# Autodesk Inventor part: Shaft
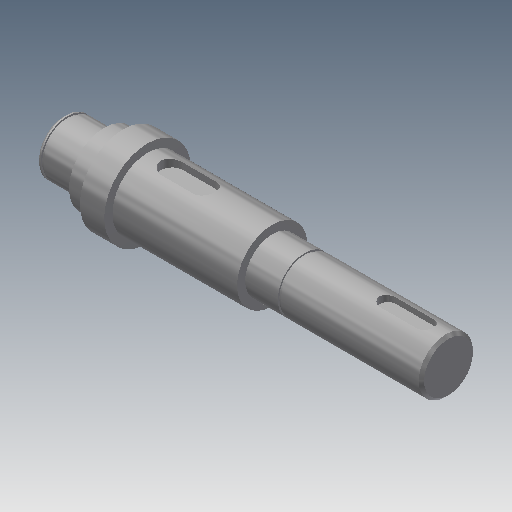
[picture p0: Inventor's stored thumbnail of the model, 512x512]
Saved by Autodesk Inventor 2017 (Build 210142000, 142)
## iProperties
Created: 2019-02
Part Number: Shaft
Material: Steel
Document SubType Name: Modeling
Designer: user
Density: 7.85 g/cm^3
Appearance: Steel
Mass: 468.646 g
Surface Area: 121.458 cm^2
Volume: 59.7002 cm^3
CustomPartVersion: 1
Author: user
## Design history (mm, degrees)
sketch "Main Sketch"
  geometry: L1 (0, 0)-(142, 0) reference; L2 (0, 0)-(0, 10); L3 (0, 10)-(15, 10); L4 (15, 10)-(15, 13); L5 (15, 13)-(22, 13); L6 (22, 13)-(22, 16); L7 (22, 16)-(31, 16); L8 (31, 16)-(31, 13); L9 (31, 13)-(61, 13); L10 (77, 13)-(77, 10); L11 (61, 13)-(77, 13); L12 (142, 10)-(142, 0); L13 (77, 10)-(142, 10)
  constraints: 26 end point, 6 vertical, 1 horizontal
  dimensions: "d3" = 20 diameter of L3 L1 (derived); "d4" = 26 diameter of L5 L1 (derived); "d5" = 32 diameter of L7 L1 (derived); "d6" = 26 diameter of L9 L1 (derived); "d7" = 26 diameter of L11 L1 (derived); "d8" = 20 diameter of L13 L1 (derived)
revolve "Revolution1" sketch "Main Sketch" stored, may be unused: angle "d9" = 0 deg
node "Keyway1"
node "Keyway2"
chamfer "Chamfer3" distance "d16" = 1; stored, may be unused: second distance "d17" = 0.125, angle "d18" = 45 deg
node "Retaining Ring Groove1"
chamfer "Chamfer2" distance "d13" = 1; stored, may be unused: second distance "d14" = 0.125, angle "d15" = 45 deg
node "Retaining Ring Groove2"
body "Solid1"
feature "iFeature27:1"
feature "iFeature27:2"
feature "iFeature3:1"
feature "iFeature3:2"
other parameters: "d0" = 0, "d1" = 0, "d2" = 0
